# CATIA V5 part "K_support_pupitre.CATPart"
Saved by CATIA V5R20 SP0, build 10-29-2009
Part number: support_pupitre
Bounding box of the stored display mesh (mm): x -57.353 to -35.218, y -10 to -2, z -40.379 to 60.094
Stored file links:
  G:\Khaled_CFAO_2011\ST2M\ST2M_GR2\gcausse\Khaled\CAD_ThinkMotion\K_support_pupitre.CATPart
  C:\Documents and Settings\gcausse\Bureau\video thinkmotio\assemblage_gcausse\pupitre_think.CATProduct
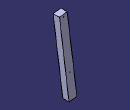
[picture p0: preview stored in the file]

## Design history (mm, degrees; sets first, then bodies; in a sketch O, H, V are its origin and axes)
Set1
  Sketch1 on Plane1, origin (0, -2, 0), H (-1, 0, 0), V (0, 0, 1)
    line L1 (35.2181, 58.873) -> (45.1433, 60.094)
    line L2 (45.1433, 60.094) -> (57.3532, -39.1578)
    line L3 (57.3532, -39.1578) -> (47.428, -40.3788)
    line L4 (47.428, -40.3788) -> (35.2181, 58.873)
    reference projected line E1 (40.547, 56.5059) -> (52.1464, -37.7833) from Line1
    reference projected point E2 (40.547, 56.5059) from Point1
    reference projected point E3 (40.547, 56.5059) from Point1
    distance L2 L4 = 10
    length L4 = 100
    length L2 = 100
    distance L1 E3 = 3
    perpendicularity: L2 L1
    parallelism: L2 E1
    equidistance: L4 L2 E2
Set2
  Plane1: linked copy from another document
  Line1: linked copy from another document
  Point1 to Point4: linked copy from another document
Set3
  Point5: type Center, Curve edge [end face of Pad2 | face of Pad2 from Sketch2.A1]
  Point6: type Center, Curve edge [end face of Pad2 | face of Pad2 from Sketch2.A2]
  Line2: type PtPt, FirstPoint Point5, SecondPoint Point6
  Plane2: type Tangent, Support face of Pad1 from Sketch1.L2, RefPoint Point2
Body1 (main body)
  Pad1: profile Sketch1, direction (0, 1, 0), length -8
  Sketch2 on face of Pad1 from Sketch1.L2, origin (-57.3532, -2, -39.1578), H (0.1221, 0, 0.9925), V (0, -1, 0)
    circle A1 centre (32, 4) radius 0.5
    point P1 (32, 4)
    reference projected point E1 (32, 4) from Point2
    circle A2 centre (27, 4) radius 0.5
    point P2 (27, 4)
    reference projected point E2 (27, 4) from Point3
    coincidence: P1 E1, P2 E2
  Pad2: profile Sketch2, direction (-0.9925, 0, 0.1221), length 2
  Sketch3 on start face of Pad1, origin (-41.7192, -2, 56.875), H (1, 0, 0), V (0, 0, -1)
    point P1 (1.1722, 0.3691)
    reference projected point E1 (1.1722, 0.3691) from Point1
    coincidence: P1 E1
  Hole1: placed by Sketch3, at (-40.547, -2, 56.5059) direction (0, -1, 0), diameter 1, depth 8
  Sketch4 on start face of Pad1, origin (-49.1945, -2, -9.1374), H (1, 0, 0), V (0, 0, -1)
    point P1 (0.7111, -1.1296)
    reference projected point E1 (0.7111, -1.1296) from Point4
    coincidence: P1 E1
  Hole2: placed by Sketch4, at (-48.4834, -2, -8.0078) direction (0, -1, 0), diameter 1, depth 8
